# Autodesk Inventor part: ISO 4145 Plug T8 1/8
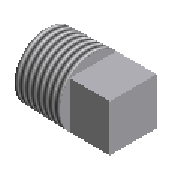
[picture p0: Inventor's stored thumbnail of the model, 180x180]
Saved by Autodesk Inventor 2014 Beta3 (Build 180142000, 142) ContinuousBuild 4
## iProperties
IsCustomPart: 0
Created: 2010-02
Part Number: ISO 4145 Plug T8 1/8
Material: Steel, Non-Alloy
Description: ISO 4145 Non-alloy steel fittings threaded to ISO 7/1 - Plug T8
Document SubType Name: Modeling
Standard: ISO 4145
Designer: Thom Tremblay
Standard Revision: Second edition 1986-07-15
Standards Organization: ISO
Language: en-US
Size Designation: 1/8
Categories: <MemberInstance><Categories><Category DisplayName="Tube &amp; Pipe" InternalName="4347fa0f-2144-441d-94cd-e3e15c92b736" Mnemonic="TUBEANDPIPE"><CategoryParamete
Density: 1 g/cm^3
Appearance: Semi-Polished
NAME: PIPING: ISO 4145 Plug T8
DATA: <meta><inlinegroups number="0" deflen="0"></inlinegroups><connections number="1"></connections><angles></angles></meta>
Author: Thom Tremblay
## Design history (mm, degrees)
sketch "Sketch1"
  geometry: L1 (0, 0)-(-7, 0); L2 (0, 4.74)-(0, 0); L3 (0, 4.74)-(-7, 4.959); L4 (-7, 4.959)-(-7, 0); L5 (-3.97, 4.864)-(-3.97, 0)
  constraints: 10 end point, 2 point on line, 1 horizontal, 1 perpendicular, 1 vertical
  dimensions: "d0" = 7 distance between parallel lines of L2 L4 (= L - n); "d1" = 1.78991 deg angle of L1 L3; "d12" = 3.97 distance between parallel lines of L2 L5 (= a); "d13" = 9.728 diameter of L5.start L1 (= MjD)
revolve "Revolve1" sketch "Sketch1" stored, may be unused: angle "d4" = 90 deg
sketch "Sketch2"
  geometry: C1 r 4.74 at (0, 0) reference; C2 r 4.3 at (0, 0)
  constraints: 1 centre point, 1 coincident, 1 concentric
  dimensions: "d2" = 8.6 diameter of C2 (= d3)
extrude "Extrude1" cut sketch "Sketch2" distance "d5" = 6 (= -n + L - k); taper "d6" = 0 deg
thread "Thread1" dims "d8" = 10, "d9" = 0
sketch "Sketch3"
  geometry: L1 (-3.5, -3.5)-(3.5, -3.5); L2 (3.5, -3.5)-(3.5, 3.5); L3 (3.5, 3.5)-(-3.5, 3.5); L4 (-3.5, 3.5)-(-3.5, -3.5); L5 (-3.5, -3.5)-(3.5, 3.5); L6 (3.5, -3.5)-(-3.5, 3.5); C1 r 4.959 at (0, 0) reference; 1 further point
  constraints: 12 end point, 2 parallel, 2 perpendicular, 1 coincident, 1 horizontal, 1 midpoint
  dimensions: "d7" = 7 distance of L2.end L3.end (= S1)
extrude "Extrude2" join sketch "Sketch3" distance "d10" = 6 (= n); taper "d11" = 0 deg
workaxis "Work Axis1"
workpoint "Work Point1"
workaxis "Work Axis2"
workpoint "Work Point2"
body "Solid1"
other parameters: "L" = 13 [user parameter; used in 2 equation terms], "n" = 6 [user parameter; used in 3 equation terms], "d3" = 8.6 [user parameter; used in 1 equation term], "k" = 1 [user parameter; used in 1 equation term], "S1" = 7 [user parameter; used in 1 equation term], "a" = 3.97 [user parameter; used in 1 equation term], "MjD" = 9.728 [user parameter; used in 1 equation term], "a1" = 2.5 [user parameter], "Size_Designation" = 1.25 [user parameter]
